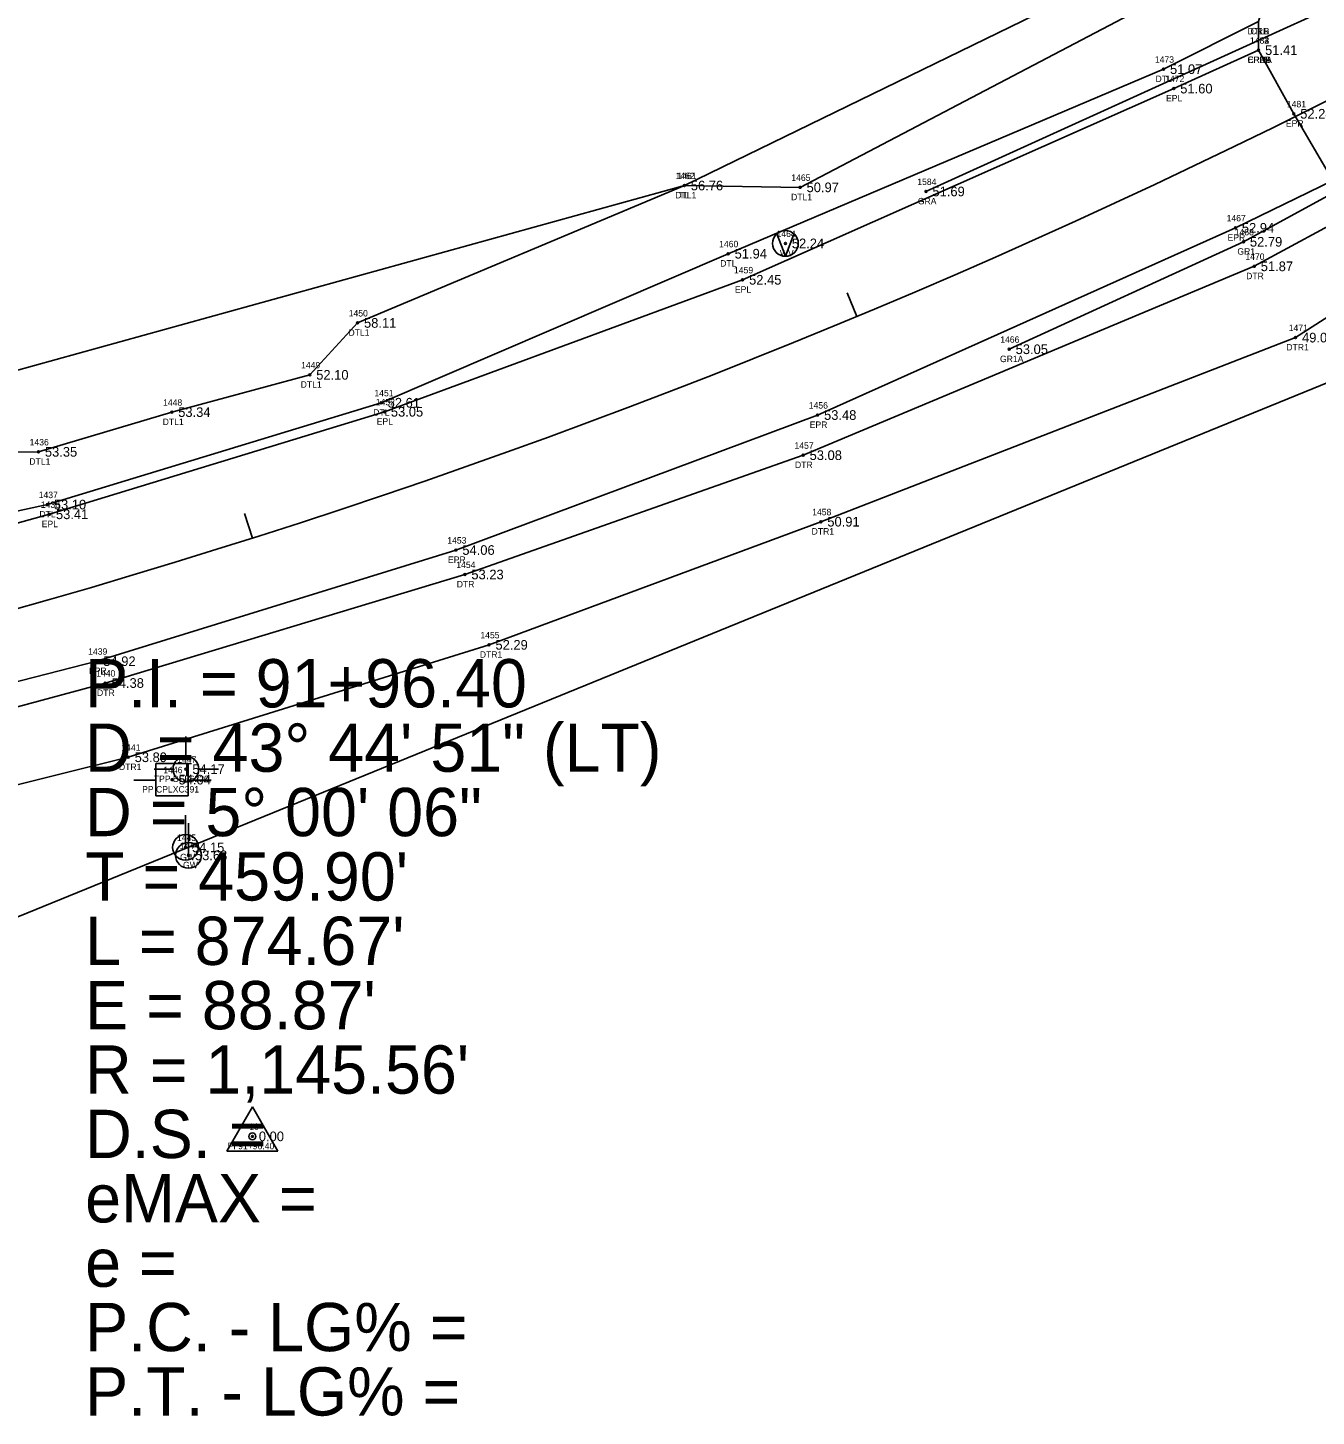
# Model space of a CAD drawing. Extents: x 2420113 to 2422887, y 845323 to 846653.
# Drawn here: x 2421548.1 to 2421748.2, y 845595.9 to 845811.6 of the extents above; entities that cross this region are included whole.
import ezdxf

# ---------------------------------------------------------------- set-up
doc = ezdxf.new("R2010")
doc.units = 0
for name, color, linetype in [('RD_EX_GuardRail', 7, 'Continuous'), ('RD_EX_GuardRail_txCode', 7, 'Continuous'), ('RD_EX_H2O', 7, 'Continuous'), ('RD_EX_H2O_txCode', 7, 'Continuous'), ('RD_EX_Road', 7, 'Continuous'), ('RD_EX_Road_txCode', 7, 'Continuous'), ('RD_EX_TX_GuardRail_ELEV', 7, 'Continuous'), ('RD_EX_TX_H2O_ELEV', 7, 'Continuous'), ('RD_EX_TX_Road_ELEV', 7, 'Continuous'), ('RD_EX_TX_UT_ELEV', 7, 'Continuous'), ('RD_EX_TX_VEG_ELEV', 7, 'Continuous'), ('RD_EX_UT', 7, 'Continuous'), ('RD_EX_UT_txCode', 7, 'Continuous'), ('RD_EX_VEG', 7, 'Continuous'), ('RD_EX_VEG_txCode', 7, 'Continuous'), ('RD_HC_Cl', 7, 'Continuous'), ('RD_HC_Data', 7, 'Continuous'), ('RD_HC_Data_Tic', 7, 'Continuous'), ('RD_HC_Survey_ELEV', 7, 'Continuous'), ('RD_HC_txCode', 7, 'Continuous'), ('RD_SMD_Locator', 7, 'Continuous')]:
    doc.layers.add(name, color=color, linetype=linetype)

msp = doc.modelspace()

# ---------------------------------------------------------------- linework, layer by layer
at = {"layer": 'RD_EX_GuardRail'}
for points in [[(2421687.56, 845786.15), (2421753.19, 845816.01), (2421776.46, 845828.5), (2421792.19, 845836.93), (2421803.2, 845843.9), (2421853.09, 845876.29)], [(2421700.48, 845761.64), (2421736.86, 845778.33), (2421765.25, 845793.79), (2421765.25, 845793.79), (2421804.57, 845814.88), (2421817.05, 845820.87), (2421867.07, 845850.23)]]:
    msp.add_lwpolyline(points, dxfattribs=at)
at = {"layer": 'RD_EX_H2O'}
for points in [[(2420975.55, 846190.58), (2420976.37, 846105.11), (2420974.31, 845997.82), (2420976.03, 845896.74), (2420974.59, 845794.18), (2420975.37, 845743.63), (2420984.12, 845720.99), (2420999.91, 845711.18), (2421116.7, 845699.77), (2421177.35, 845696.01), (2421236.57, 845694.11), (2421292.07, 845694.75), (2421349.67, 845700.43), (2421411.57, 845706.56), (2421470.63, 845718.76), (2421529.96, 845732.93), (2421551.14, 845737.51), (2421602.97, 845753.33), (2421656.85, 845776.48), (2421724.45, 845805.15), (2421739.21, 845812.56)], [(2421739.21, 845808.11), (2421739.21, 845812.56), (2421742.22, 845823.45), (2421740.13, 845828.42), (2421727.39, 845836.73), (2421712.23, 845851.64)], [(2421348.44, 845711.4), (2421408.11, 845718.43), (2421468.58, 845729.77), (2421526.52, 845745.24), (2421541.81, 845745.64), (2421549.75, 845745.7), (2421570.45, 845751.87), (2421591.88, 845757.66), (2421599.3, 845765.73), (2421650.04, 845787.07), (2421668.02, 845786.79), (2421719.15, 845813.59), (2421740.13, 845828.42)], [(2421462.85, 845683.51), (2421560.11, 845709.79), (2421615.97, 845726.65), (2421668.49, 845745.18), (2421738.54, 845774.52), (2421754.61, 845783.24)], [(2421462.85, 845683.51), (2421463.34, 845677.36), (2421472.12, 845675.5), (2421563.69, 845698.26), (2421619.71, 845715.72), (2421671.24, 845734.85), (2421744.95, 845763.45), (2421768.08, 845778.29)]]:
    msp.add_lwpolyline(points, dxfattribs=at)
at = {"layer": 'RD_EX_Road'}
for points in [[(2420388.28, 845680.39), (2420441.29, 845692.04), (2420492.62, 845700.7), (2420553.92, 845707.41), (2420607.69, 845710.85), (2420682.38, 845711.26), (2420749.44, 845707.27), (2420795.12, 845703.44), (2420900.28, 845693.42), (2421017.17, 845682.19), (2421113.9, 845672.97), (2421174.87, 845668.16), (2421234.59, 845666.13), (2421293, 845667.25), (2421351.24, 845671.5), (2421419.82, 845681.17), (2421463.19, 845688.63), (2421558.82, 845713.18), (2421614.57, 845730.45), (2421670.73, 845751.42), (2421735.61, 845780.5), (2421750.75, 845787.87), (2421744.67, 845798.22), (2421739.21, 845808.11)], [(2421350.22, 845695.49), (2421412.35, 845704.28), (2421471.12, 845715.7), (2421530.23, 845730.14), (2421551.47, 845736), (2421603.47, 845751.93), (2421659.09, 845772.43), (2421726.04, 845802.13), (2421739.21, 845808.11)]]:
    msp.add_lwpolyline(points, dxfattribs=at)
at = {"layer": 'RD_EX_UT'}
for p, q in [((2421665.73, 845776.09), (2421664.42, 845779.57)), ((2421665.73, 845776.09), (2421667.05, 845779.54)), ((2421572.65, 845701.48), (2421572.65, 845698.41)), ((2421567.72, 845696.42), (2421570.65, 845696.42)), ((2421573, 845697.29), (2421568, 845697.29)), ((2421568, 845697.29), (2421568, 845692.29)), ((2421573, 845692.29), (2421573, 845697.29)), ((2421574.65, 845696.42), (2421577.72, 845696.42)), ((2421564.57, 845694.72), (2421568.04, 845694.72)), ((2421572.93, 845694.72), (2421576.57, 845694.72)), ((2421568, 845692.29), (2421573, 845692.29)), ((2421572.59, 845684.26), (2421572.59, 845689.26)), ((2421573.05, 845683.02), (2421573.05, 845688.02))]:
    msp.add_line(p, q, dxfattribs=at)
for centre in [(2421665.73, 845778.08), (2421572.65, 845696.41), (2421572.59, 845684.26), (2421573.05, 845683.02)]:
    msp.add_circle(centre, 2, dxfattribs=at)
at = {"layer": 'RD_EX_VEG'}
for points in [[(2420990.17, 846190.24), (2420988, 845998.32), (2421000.67, 845894.83), (2421039.72, 845794.91), (2421064.26, 845723.75), (2421180.05, 845716.6), (2421345.47, 845727.16), (2421407.77, 845719.99), (2421650.04, 845787.07), (2421772.66, 845846.85), (2421772.66, 845846.85), (2421889.56, 845912.24), (2422060.37, 846045.26), (2422197.94, 846165.23), (2422281.92, 846227.58), (2422364.58, 846286.67), (2422339.46, 846334.5)], [(2421514.28, 845601.29), (2421515.71, 845632.65), (2421540.03, 845670.81), (2421822.4, 845786.03), (2421822.4, 845786.03), (2421928.63, 845815.98), (2422026.48, 845905.33), (2422114.13, 845963.57), (2422135.16, 845938.99)]]:
    msp.add_lwpolyline(points, dxfattribs=at)
at = {"layer": 'RD_HC_Cl'}
msp.add_arc((2421235.71, 846823.95), 1145.56, 264.46476, 308.21213, dxfattribs=at)
at = {"layer": 'RD_HC_Data'}
for p, q in [((2421579, 845637.08), (2421582.97, 845643.96)), ((2421582.97, 845643.96), (2421586.94, 845637.08)), ((2421579, 845637.08), (2421586.94, 845637.08))]:
    msp.add_line(p, q, dxfattribs=at)
msp.add_circle((2421582.97, 845639.37), 0.529, dxfattribs=at)
at = {"layer": 'RD_HC_Data_Tic'}
for p, q in [((2421676.84, 845766.73), (2421675.3, 845770.42)), ((2421582.99, 845732.29), (2421581.77, 845736.11))]:
    msp.add_line(p, q, dxfattribs=at)
at = {"layer": 'RD_SMD_Locator'}
for centre in [(2421739.21, 845808.11), (2421739.21, 845808.11), (2421739.21, 845808.11), (2421724.45, 845805.15), (2421726.04, 845802.13), (2421744.67, 845798.22), (2421650.04, 845787.07), (2421650.04, 845787.07), (2421668.02, 845786.79), (2421687.56, 845786.15), (2421735.61, 845780.5), (2421665.73, 845778.08), (2421736.86, 845778.33), (2421656.85, 845776.48), (2421738.54, 845774.52), (2421659.09, 845772.43), (2421599.3, 845765.73), (2421744.95, 845763.45), (2421700.48, 845761.64), (2421591.88, 845757.66), (2421570.45, 845751.87), (2421602.97, 845753.33), (2421603.47, 845751.93), (2421670.73, 845751.42), (2421549.75, 845745.7), (2421668.49, 845745.18), (2421551.14, 845737.51), (2421551.47, 845736), (2421671.24, 845734.85), (2421614.57, 845730.45), (2421615.97, 845726.65), (2421619.71, 845715.72), (2421558.82, 845713.18), (2421560.11, 845709.79), (2421563.69, 845698.26), (2421572.65, 845696.41), (2421570.51, 845694.78), (2421572.59, 845684.26), (2421573.05, 845683.02), (2421582.97, 845639.37)]:
    msp.add_circle(centre, 0.15, dxfattribs=at)

# ---------------------------------------------------------------- texts
at = {"layer": 'RD_EX_GuardRail_txCode'}
for s, p in [('1584', (2421686.21, 845787.15)), ('GRA', (2421686.29, 845784.15)), ('1468', (2421735.49, 845779.33)), ('GR1', (2421735.91, 845776.33)), ('1466', (2421699.09, 845762.64)), ('GR1A', (2421699.05, 845759.64))]:
    msp.add_text(s, height=1, dxfattribs=at).set_placement(p)
at = {"layer": 'RD_EX_H2O_txCode'}
for s, p in [('DTLB', (2421737.49, 845810.56)), ('CRR', (2421737.96, 845810.56)), ('1484', (2421737.87, 845809.11)), ('1473', (2421723.1, 845806.15)), ('CRRA', (2421737.47, 845806.11)), ('DTL', (2421723.2, 845803.15)), ('1461', (2421648.95, 845788.07)), ('1465', (2421666.65, 845787.79)), ('DTL1', (2421648.63, 845785.07)), ('DTL1', (2421666.61, 845784.79)), ('1460', (2421655.44, 845777.48)), ('1470', (2421737.15, 845775.52)), ('DTL', (2421655.61, 845774.48)), ('DTR', (2421737.27, 845772.52)), ('1450', (2421597.92, 845766.73)), ('1471', (2421743.88, 845764.45)), ('DTL1', (2421597.89, 845763.73)), ('DTR1', (2421743.51, 845761.45)), ('1449', (2421590.53, 845758.66)), ('DTL1', (2421590.47, 845755.66)), ('1451', (2421601.91, 845754.33)), ('1448', (2421569.1, 845752.87)), ('DTL', (2421601.73, 845751.33)), ('DTL1', (2421569.04, 845749.87)), ('1436', (2421548.38, 845746.7)), ('1457', (2421667.14, 845746.18)), ('DTL1', (2421548.34, 845743.7)), ('DTR', (2421667.22, 845743.18)), ('1437', (2421549.79, 845738.51)), ('1458', (2421669.89, 845735.85)), ('DTL', (2421549.89, 845735.51)), ('DTR1', (2421669.8, 845732.85)), ('1454', (2421614.63, 845727.65)), ('DTR', (2421614.7, 845724.65)), ('1455', (2421618.37, 845716.72)), ('DTR1', (2421618.28, 845713.72)), ('1440', (2421558.72, 845710.79)), ('DTR', (2421558.84, 845707.79)), ('1441', (2421562.62, 845699.26)), ('DTR1', (2421562.25, 845696.26))]:
    msp.add_text(s, height=1, dxfattribs=at).set_placement(p)
at = {"layer": 'RD_EX_Road_txCode'}
for s, p in [('1482', (2421737.87, 845809.11)), ('1483', (2421737.87, 845809.11)), ('EPRB', (2421737.51, 845806.11)), ('EPLB', (2421737.54, 845806.11)), ('1472', (2421724.69, 845803.13)), ('EPL', (2421724.83, 845800.13)), ('1481', (2421743.6, 845799.22)), ('EPR', (2421743.44, 845796.22)), ('1467', (2421734.24, 845781.5)), ('EPR', (2421734.38, 845778.5)), ('1459', (2421657.75, 845773.43)), ('EPL', (2421657.89, 845770.43)), ('1452', (2421602.12, 845752.93)), ('1456', (2421669.36, 845752.42)), ('EPL', (2421602.27, 845749.93)), ('EPR', (2421669.5, 845749.42)), ('1438', (2421550.12, 845737)), ('EPL', (2421550.26, 845734)), ('1453', (2421613.23, 845731.45)), ('EPR', (2421613.34, 845728.45)), ('1439', (2421557.47, 845714.18)), ('EPR', (2421557.59, 845711.18))]:
    msp.add_text(s, height=1, dxfattribs=at).set_placement(p)
at = {"layer": 'RD_EX_TX_GuardRail_ELEV'}
for s, p in [('51.69', (2421688.56, 845785.4)), ('52.79', (2421737.86, 845777.58)), ('53.05', (2421701.48, 845760.89))]:
    msp.add_text(s, height=1.5, dxfattribs=at).set_placement(p)
at = {"layer": 'RD_EX_TX_H2O_ELEV'}
for s, p in [('51.41', (2421740.21, 845807.36)), ('51.07', (2421725.45, 845804.4)), ('56.76', (2421651.04, 845786.32)), ('50.97', (2421669.02, 845786.04)), ('51.94', (2421657.85, 845775.73)), ('51.87', (2421739.54, 845773.77)), ('58.11', (2421600.3, 845764.98)), ('49.03', (2421745.95, 845762.7)), ('52.10', (2421592.88, 845756.91)), ('52.61', (2421603.97, 845752.58)), ('53.34', (2421571.45, 845751.12)), ('53.35', (2421550.75, 845744.95)), ('53.08', (2421669.49, 845744.43)), ('53.10', (2421552.14, 845736.76)), ('50.91', (2421672.24, 845734.1)), ('53.23', (2421616.97, 845725.9)), ('52.29', (2421620.71, 845714.97)), ('54.38', (2421561.11, 845709.04)), ('53.89', (2421564.69, 845697.51))]:
    msp.add_text(s, height=1.5, dxfattribs=at).set_placement(p)
at = {"layer": 'RD_EX_TX_Road_ELEV'}
for s, p in [('51.41', (2421740.21, 845807.36)), ('51.41', (2421740.21, 845807.36)), ('51.60', (2421727.04, 845801.38)), ('52.24', (2421745.67, 845797.47)), ('52.94', (2421736.61, 845779.75)), ('52.45', (2421660.09, 845771.68)), ('53.05', (2421604.47, 845751.18)), ('53.48', (2421671.73, 845750.67)), ('53.41', (2421552.47, 845735.25)), ('54.06', (2421615.57, 845729.7)), ('54.92', (2421559.82, 845712.43))]:
    msp.add_text(s, height=1.5, dxfattribs=at).set_placement(p)
at = {"layer": 'RD_EX_TX_UT_ELEV'}
for s, p in [('52.24', (2421666.73, 845777.33)), ('54.17', (2421573.65, 845695.66)), ('54.15', (2421573.59, 845683.51)), ('53.68', (2421574.05, 845682.27))]:
    msp.add_text(s, height=1.5, dxfattribs=at).set_placement(p)
at = {"layer": 'RD_EX_TX_VEG_ELEV'}
msp.add_text('56.76', height=1.5, dxfattribs=at).set_placement((2421651.04, 845786.32))
at = {"layer": 'RD_EX_UT'}
msp.add_text('T', height=2, dxfattribs=at).set_placement((2421571.98, 845695.36))
at = {"layer": 'RD_EX_UT_txCode'}
for s, p in [('1464', (2421664.36, 845779.08)), ('WV', (2421664.87, 845776.08)), ('1447', (2421571.3, 845697.41)), ('1446', (2421569.14, 845695.78)), ('PP CPLXC391', (2421565.85, 845692.78)), ('TPP BSF6220', (2421567.66, 845694.41)), ('1445', (2421571.25, 845685.26)), ('1444', (2421571.7, 845684.02)), ('GW', (2421571.75, 845682.26)), ('GW', (2421572.2, 845681.02))]:
    msp.add_text(s, height=1, dxfattribs=at).set_placement(p)
at = {"layer": 'RD_EX_VEG_txCode'}
for s, p in [('1462', (2421648.67, 845788.07)), ('TL', (2421649.27, 845785.07))]:
    msp.add_text(s, height=1, dxfattribs=at).set_placement(p)
at = {"layer": 'RD_HC_Data'}
for s, p in [('P.I. = 91+96.40', (2421557, 845706)), ('D', (2421557, 845696)), ('    = 43%%d 44\' 51" (LT)', (2421557, 845696)), ('D = 5%%d 00\' 06"', (2421557, 845686)), ("T = 459.90'", (2421557, 845676)), ("L = 874.67'", (2421557, 845666)), ("E = 88.87'", (2421557, 845656)), ("R = 1,145.56'", (2421557, 845646)), ('D.S. = ', (2421557, 845636)), ('eMAX = ', (2421557, 845626)), ('e = ', (2421557, 845616)), ('P.C. - LG% = ', (2421557, 845606)), ('P.T. - LG% = ', (2421557, 845596))]:
    msp.add_text(s, height=7.5, dxfattribs=at).set_placement(p)
at = {"layer": 'RD_HC_Survey_ELEV'}
for s, p in [('54.04', (2421571.51, 845694.03)), ('0.00', (2421583.97, 845638.62))]:
    msp.add_text(s, height=1.5, dxfattribs=at).set_placement(p)
at = {"layer": 'RD_HC_txCode'}
for s, p in [('10', (2421582.48, 845640.37)), ('PI 91+96.40', (2421579.12, 845637.37))]:
    msp.add_text(s, height=1, dxfattribs=at).set_placement(p)

doc.saveas('drawing.dxf')
